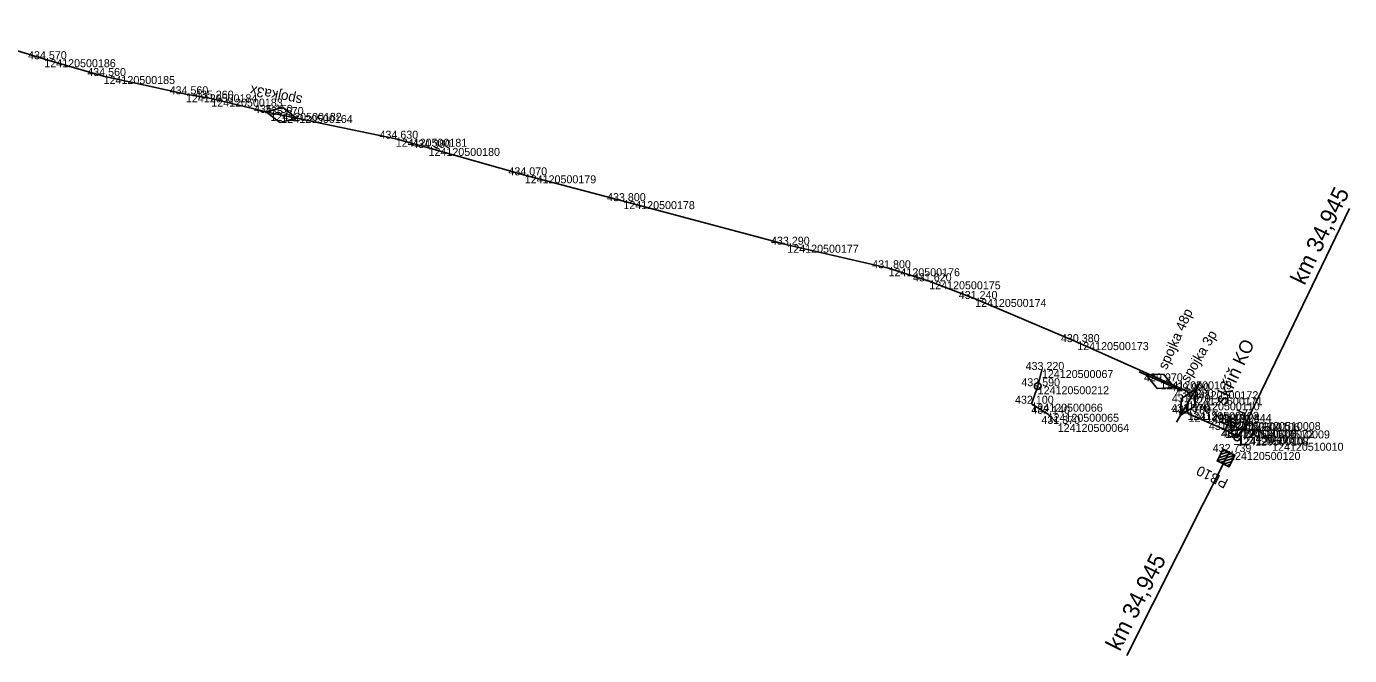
# Model space of a CAD drawing. Extents: x -637342 to -635997, y -1153616 to -1153154.
# Drawn here: x -636195.2 to -635996.7, y -1153616 to -1153521.6 of the extents above; entities that cross this region are included whole.
import ezdxf

# ---------------------------------------------------------------- set-up
doc = ezdxf.new("R2010")
doc.units = 0
for name, color, linetype in [('Vrstva 25', 7, 'Continuous'), ('Vrstva 26', 7, 'Continuous'), ('Vrstva 27', 7, 'Continuous'), ('Vrstva 28', 7, 'Continuous'), ('Vrstva 3', 7, 'Continuous'), ('Vrstva 6', 7, 'Continuous'), ('Vrstva 60', 7, 'Continuous'), ('Vrstva 61', 7, 'Continuous')]:
    doc.layers.add(name, color=color, linetype=linetype)

msp = doc.modelspace()

# ---------------------------------------------------------------- linework, layer by layer
at = {"layer": 'Vrstva 25'}
msp.add_line((-636043.48, -1153575.58), (-636043.5, -1153575.68), dxfattribs=at)
msp.add_circle((-636043.49, -1153575.63), 0.5, dxfattribs=at)
at = {"layer": 'Vrstva 26'}
for points in [[(-636040.48, -1153581.28), (-636042, -1153579.76), (-636044.44, -1153578.25), (-636043.49, -1153575.63), (-636042.85, -1153573.19)], [(-636008.33, -1153584.11), (-636010.37, -1153582.26), (-636011.76, -1153581.01), (-636012.77, -1153582.2)]]:
    msp.add_lwpolyline(points, dxfattribs=at)
at = {"layer": 'Vrstva 27'}
for p, q in [((-636015.64, -1153580.4), (-636015.63, -1153580.4)), ((-636013.52, -1153583.35), (-636013.6, -1153583.31))]:
    msp.add_line(p, q, dxfattribs=at)
msp.add_lwpolyline([(-636015.64, -1153580.4), (-636013.83, -1153581.26), (-636014.12, -1153581.86), (-636015.93, -1153581)], close=True, dxfattribs=at)
msp.add_lwpolyline([(-636014.75, -1153580.08), (-636014.74, -1153580.83), (-636014.15, -1153580.37)], dxfattribs=at)
msp.add_circle((-636013.56, -1153583.33), 0.5, dxfattribs=at)
at = {"layer": 'Vrstva 28'}
for p, q in [((-636153.52, -1153535.62), (-636160.36, -1153534.22)), ((-636159.22, -1153534.45), (-636156.7, -1153533.78)), ((-636157.18, -1153536.06), (-636159.22, -1153534.45)), ((-636156.7, -1153533.78), (-636154.66, -1153535.39)), ((-636154.66, -1153535.39), (-636157.18, -1153536.06)), ((-636021.89, -1153576.32), (-636028.27, -1153573.46)), ((-636027.2, -1153573.94), (-636024.6, -1153573.83)), ((-636025.56, -1153575.95), (-636027.2, -1153573.94)), ((-636024.6, -1153573.83), (-636022.96, -1153575.84)), ((-636022.96, -1153575.84), (-636025.56, -1153575.95)), ((-636022.69, -1153581.04), (-636019.13, -1153575.04)), ((-636021.91, -1153577.45), (-636019.72, -1153576.04)), ((-636019.72, -1153576.04), (-636019.91, -1153578.63)), ((-636022.1, -1153580.04), (-636021.91, -1153577.45)), ((-636019.91, -1153578.63), (-636022.1, -1153580.04)), ((-636013.38, -1153583.19), (-636012.77, -1153582.2))]:
    msp.add_line(p, q, dxfattribs=at)
for points in [[(-636021.02, -1153579.48), (-636020.91, -1153578.04), (-636020.46, -1153577.28), (-636021.11, -1153576.37), (-636037.55, -1153569.01), (-636052.88, -1153562.53), (-636059.75, -1153559.88), (-636065.86, -1153557.92), (-636081.04, -1153554.39), (-636105.63, -1153547.85), (-636120.42, -1153543.97), (-636134.85, -1153539.86), (-636139.76, -1153538.48), (-636158.58, -1153534.6), (-636167.44, -1153532.46), (-636171.24, -1153531.81), (-636183.59, -1153529.07), (-636192.48, -1153526.55), (-636206.06, -1153522.34), (-636207.51, -1153522.06), (-636209.15, -1153521.63)], [(-636021.02, -1153579.48), (-636020.86, -1153579.76), (-636015.36, -1153582.19), (-636014.88, -1153581.13)], [(-636015.36, -1153582.19), (-636013.38, -1153583.19), (-636013.56, -1153583.33)]]:
    msp.add_lwpolyline(points, dxfattribs=at)
at = {"layer": 'Vrstva 3'}
for p, q in [((-636014.79, -1153585.5), (-636030.13, -1153616.05)), ((-636016.58, -1153586.84), (-636013.9, -1153585.95)), ((-636016.34, -1153586.37), (-636014.37, -1153585.71)), ((-636016.11, -1153587.08), (-636014.13, -1153586.42)), ((-636016.1, -1153585.89), (-636014.84, -1153585.47)), ((-636015.87, -1153585.42), (-636015.32, -1153585.24)), ((-636015.63, -1153587.32), (-636014.37, -1153586.9)), ((-636015.16, -1153587.55), (-636014.61, -1153587.37))]:
    msp.add_line(p, q, dxfattribs=at)
msp.add_lwpolyline([(-636015.68, -1153585.05), (-636013.9, -1153585.95), (-636014.79, -1153587.74), (-636016.58, -1153586.84)], close=True, dxfattribs=at)
at = {"layer": 'Vrstva 6'}
for p, q in [((-636012.77, -1153582.2), (-635996.71, -1153548.93)), ((-636014.55, -1153581.34), (-636012.77, -1153582.2)), ((-636012.99, -1153582.65), (-636012.55, -1153581.75))]:
    msp.add_line(p, q, dxfattribs=at)
at = {"layer": 'Vrstva 60'}
for p, q in [((-636192.48, -1153526.55), (-636192.48, -1153526.55)), ((-636183.59, -1153529.07), (-636183.59, -1153529.07)), ((-636171.24, -1153531.81), (-636171.24, -1153531.81)), ((-636167.44, -1153532.46), (-636167.44, -1153532.46)), ((-636158.58, -1153534.6), (-636158.58, -1153534.6)), ((-636156.94, -1153534.92), (-636156.94, -1153534.92)), ((-636139.76, -1153538.48), (-636139.76, -1153538.48)), ((-636134.85, -1153539.86), (-636134.85, -1153539.86)), ((-636120.42, -1153543.97), (-636120.42, -1153543.97)), ((-636105.63, -1153547.85), (-636105.63, -1153547.85)), ((-636081.04, -1153554.39), (-636081.04, -1153554.39)), ((-636065.86, -1153557.92), (-636065.86, -1153557.92)), ((-636059.75, -1153559.88), (-636059.75, -1153559.88)), ((-636052.88, -1153562.53), (-636052.88, -1153562.53)), ((-636037.55, -1153569.01), (-636037.55, -1153569.01)), ((-636042.85, -1153573.19), (-636042.85, -1153573.19)), ((-636043.49, -1153575.63), (-636043.49, -1153575.63)), ((-636025.08, -1153574.89), (-636025.08, -1153574.89)), ((-636021.11, -1153576.37), (-636021.11, -1153576.37)), ((-636044.44, -1153578.25), (-636044.44, -1153578.25)), ((-636020.91, -1153578.04), (-636020.91, -1153578.04)), ((-636020.46, -1153577.28), (-636020.46, -1153577.28)), ((-636042, -1153579.76), (-636042, -1153579.76)), ((-636021.02, -1153579.48), (-636021.02, -1153579.48)), ((-636020.86, -1153579.76), (-636020.86, -1153579.76)), ((-636040.48, -1153581.28), (-636040.48, -1153581.28)), ((-636015.36, -1153582.19), (-636015.36, -1153582.19)), ((-636014.88, -1153581.13), (-636014.88, -1153581.13)), ((-636012.77, -1153582.2), (-636012.77, -1153582.2)), ((-636011.76, -1153581.01), (-636011.76, -1153581.01)), ((-636010.37, -1153582.26), (-636010.37, -1153582.26)), ((-636013.56, -1153583.33), (-636013.56, -1153583.33)), ((-636013.38, -1153583.19), (-636013.38, -1153583.19)), ((-636008.33, -1153584.11), (-636008.33, -1153584.11)), ((-636014.79, -1153585.5), (-636014.79, -1153585.5))]:
    msp.add_line(p, q, dxfattribs=at)

# ---------------------------------------------------------------- texts
at = {"layer": 'Vrstva 27'}
msp.add_text('skříň KO', height=2, rotation=65.0454, dxfattribs=at).set_placement((-636015.3, -1153578.61))
at = {"layer": 'Vrstva 28'}
for s, rotation, p in [('spojka3x', 168.3509, (-636153.69, -1153532.07)), ('spojka 48p', 65.8318, (-636024.15, -1153573.25)), ('spojka 3p', 59.37, (-636020.88, -1153575.19))]:
    msp.add_text(s, height=1.5, rotation=rotation, dxfattribs=at).set_placement(p)
at = {"layer": 'Vrstva 3'}
for s, height, rotation, p in [('PB10', 1.5, 153.37, (-636014.79, -1153589.69)), ('km 34,945', 2.5, 63.3313, (-636031.17, -1153615.52))]:
    msp.add_text(s, height=height, rotation=rotation, dxfattribs=at).set_placement(p)
at = {"layer": 'Vrstva 6'}
for s, height, rotation, p in [('km 34,945', 2.5, 64.2395, (-636003.46, -1153560.59)), ('  A A A A A ', 1, 154.1906, (-636012.33, -1153581.3)), ('L', 1.5, 64.1906, (-636012.41, -1153580.05))]:
    msp.add_text(s, height=height, rotation=rotation, dxfattribs=at).set_placement(p)
at = {"layer": 'Vrstva 60'}
for s, p in [('124120500186', (-636192.48, -1153527.75)), ('124120500185', (-636183.59, -1153530.27)), ('124120500184', (-636171.24, -1153533.01)), ('124120500183', (-636167.44, -1153533.66)), ('124120500182', (-636158.58, -1153535.8)), ('124120500164', (-636156.94, -1153536.12)), ('124120500181', (-636139.76, -1153539.68)), ('124120500180', (-636134.85, -1153541.06)), ('124120500179', (-636120.42, -1153545.17)), ('124120500178', (-636105.63, -1153549.05)), ('124120500177', (-636081.04, -1153555.59)), ('124120500176', (-636065.86, -1153559.12)), ('124120500175', (-636059.75, -1153561.08)), ('124120500174', (-636052.88, -1153563.73)), ('124120500173', (-636037.55, -1153570.21)), ('124120500067', (-636042.85, -1153574.39)), ('124120500212', (-636043.49, -1153576.83)), ('124120500109', (-636025.08, -1153576.09)), ('124120500172', (-636021.11, -1153577.57)), ('124120500066', (-636044.44, -1153579.45)), ('124120500110', (-636020.91, -1153579.24)), ('124120500171', (-636020.46, -1153578.48)), ('124120500065', (-636042, -1153580.96)), ('124120500103', (-636021.02, -1153580.68)), ('124120500104', (-636020.86, -1153580.96)), ('124120500064', (-636040.48, -1153582.48)), ('124120500105', (-636015.36, -1153583.39)), ('124120500106', (-636014.88, -1153582.33)), ('124120500072', (-636012.77, -1153583.4)), ('124120510008', (-636011.76, -1153582.21)), ('124120510009', (-636010.37, -1153583.46)), ('124120500108', (-636013.56, -1153584.53)), ('124120500107', (-636013.38, -1153584.39)), ('124120510010', (-636008.33, -1153585.31)), ('124120500120', (-636014.79, -1153586.7))]:
    msp.add_text(s, height=1.2, dxfattribs=at).set_placement(p)
at = {"layer": 'Vrstva 61'}
for s, p in [('434.570', (-636194.93, -1153526.55)), ('434.560', (-636186.04, -1153529.07)), ('434.560', (-636173.69, -1153531.81)), ('435.260', (-636169.89, -1153532.46)), ('435.150', (-636161.03, -1153534.6)), ('435.670', (-636159.39, -1153534.92)), ('434.630', (-636142.21, -1153538.48)), ('434.380', (-636137.3, -1153539.86)), ('434.070', (-636122.87, -1153543.97)), ('433.800', (-636108.08, -1153547.85)), ('433.290', (-636083.49, -1153554.39)), ('431.800', (-636068.31, -1153557.92)), ('431.620', (-636062.2, -1153559.88)), ('431.240', (-636055.33, -1153562.53)), ('430.380', (-636040, -1153569.01)), ('433.220', (-636045.3, -1153573.19)), ('432.590', (-636045.94, -1153575.63)), ('429.970', (-636027.53, -1153574.89)), ('429.990', (-636023.56, -1153576.37)), ('430.280', (-636022.91, -1153577.28)), ('432.100', (-636046.89, -1153578.25)), ('432.140', (-636044.45, -1153579.76)), ('431.570', (-636023.47, -1153579.48)), ('431.070', (-636023.36, -1153578.04)), ('431.780', (-636023.31, -1153579.76)), ('431.370', (-636042.93, -1153581.28)), ('432.760', (-636017.33, -1153581.13)), ('431.844', (-636014.21, -1153581.01)), ('431.920', (-636017.81, -1153582.19)), ('432.790', (-636016.01, -1153583.33)), ('431.990', (-636015.83, -1153583.19)), ('432.550', (-636015.22, -1153582.2)), ('431.904', (-636012.82, -1153582.26)), ('432.739', (-636017.24, -1153585.5)), ('431.403', (-636010.79, -1153584.11))]:
    msp.add_text(s, height=1.2, dxfattribs=at).set_placement(p)

doc.saveas('drawing.dxf')
